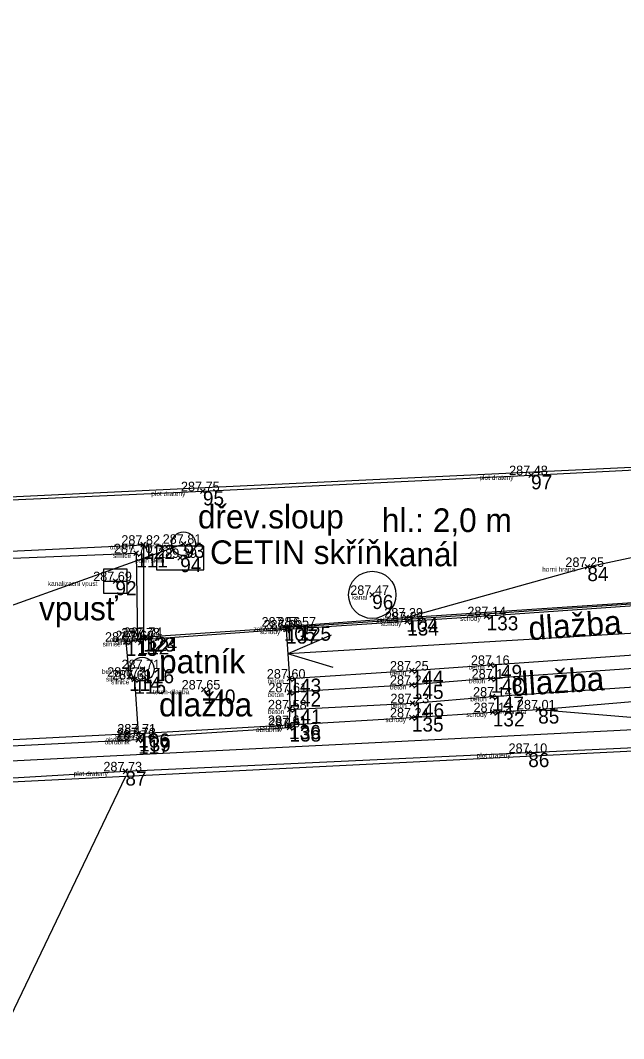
# Model space of a CAD drawing. Extents: x -456675 to -456278, y -1112395 to -1112217.
# Drawn here: x -456580.98 to -456568.22, y -1112310.75 to -1112289.23 of the extents above; entities that cross this region are included whole.
import ezdxf

# ---------------------------------------------------------------- set-up
doc = ezdxf.new("R2010")
doc.units = 0
for name, color, linetype in [('Cislo_bodu', 7, 'Continuous'), ('g_beton', 7, 'Continuous'), ('g_CETIN', 7, 'Continuous'), ('g_chodniky', 7, 'Continuous'), ('g_dalsi_prvky_polohopisu', 7, 'Continuous'), ('g_elektrina', 7, 'Continuous'), ('g_kanalizace', 7, 'Continuous'), ('g_komunikace', 7, 'Continuous'), ('g_obrubnik', 7, 'Continuous'), ('g_ploty', 7, 'Continuous'), ('g_schody', 7, 'Continuous'), ('g_terenni_hrany', 7, 'Continuous'), ('g_zabradli', 7, 'Continuous'), ('Katastralni_mapa', 7, 'Continuous'), ('Kod_bodu', 7, 'Continuous'), ('Vyska_bodu', 7, 'Continuous'), ('Znacka_bodu', 7, 'Continuous')]:
    doc.layers.add(name, color=color, linetype=linetype)

msp = doc.modelspace()

# ---------------------------------------------------------------- linework, layer by layer
at = {"layer": 'g_beton'}
for points in [[(-456575.29, -1112303.14), (-456572.7, -1112302.97), (-456571.04, -1112302.85), (-456563.45, -1112302.32), (-456560.22, -1112302.34)], [(-456560.23, -1112302.68), (-456563.48, -1112302.61), (-456571.03, -1112303.14), (-456572.7, -1112303.27), (-456575.29, -1112303.43)], [(-456575.28, -1112303.79), (-456572.69, -1112303.66), (-456571, -1112303.52), (-456563.54, -1112303.01), (-456560.25, -1112303.02)]]:
    msp.add_lwpolyline(points, dxfattribs=at)
at = {"layer": 'g_CETIN'}
msp.add_line((-456591.85, -1112305.42), (-456577.53, -1112300.29), dxfattribs=at)
msp.add_lwpolyline([(-456578.1, -1112300.84), (-456577.1, -1112300.84), (-456577.1, -1112300.34), (-456578.1, -1112300.34)], close=True, dxfattribs=at)
msp.add_circle((-456577.53, -1112300.29), 0.25, dxfattribs=at)
at = {"layer": 'g_chodniky'}
for p, q in [((-456575.36, -1112302.1), (-456578.5, -1112302.33)), ((-456578.49, -1112304.3), (-456575.3, -1112304.12))]:
    msp.add_line(p, q, dxfattribs=at)
at = {"layer": 'g_dalsi_prvky_polohopisu'}
for radius in [0.25, 0.0005]:
    msp.add_circle((-456578.401, -1112302.94), radius, dxfattribs=at)
at = {"layer": 'g_elektrina'}
msp.add_line((-456591.85, -1112305.42), (-456562.97, -1112303.96), dxfattribs=at)
at = {"layer": 'g_kanalizace'}
msp.add_line((-456579.22, -1112301.08), (-456578.72, -1112301.08), dxfattribs=at)
msp.add_lwpolyline([(-456579.22, -1112301.331), (-456578.72, -1112301.331), (-456578.72, -1112300.829), (-456579.22, -1112300.829)], close=True, dxfattribs=at)
msp.add_circle((-456573.54, -1112301.37), 0.5, dxfattribs=at)
at = {"layer": 'g_komunikace'}
msp.add_lwpolyline([(-456589.51, -1112300.93), (-456583.59, -1112300.69), (-456578.53, -1112300.49), (-456578.5, -1112302.33), (-456578.75, -1112302.36), (-456578.68, -1112303.1), (-456578.57, -1112303.16), (-456578.49, -1112304.3), (-456584.06, -1112304.58), (-456589.75, -1112304.84)], dxfattribs=at)
at = {"layer": 'g_obrubnik'}
msp.add_line((-456578.47, -1112304.38), (-456575.29, -1112304.17), dxfattribs=at)
for points in [[(-456589.47, -1112300.79), (-456583.42, -1112300.55), (-456578.38, -1112300.31), (-456578.38, -1112302.27)], [(-456578.33, -1112302.26), (-456575.08, -1112302.04), (-456563.53, -1112301.25), (-456560.31, -1112301.08)], [(-456589.79, -1112304.97), (-456584.14, -1112304.71), (-456578.49, -1112304.43)]]:
    msp.add_lwpolyline(points, dxfattribs=at)
at = {"layer": 'g_ploty'}
for points in [[(-456588.66, -1112299.7), (-456577.12, -1112299.18), (-456570.18, -1112298.84), (-456563.86, -1112298.52), (-456563.69, -1112291.41), (-456563.68, -1112287.66)], [(-456564.24, -1112317.5), (-456564.14, -1112310.05), (-456564.09, -1112304.42), (-456570.24, -1112304.71), (-456578.76, -1112305.1), (-456590.32, -1112305.79)]]:
    msp.add_lwpolyline(points, dxfattribs=at)
at = {"layer": 'g_schody'}
for p in [(-456560.195, -1112301.72), (-456574.407, -1112302.223), (-456574.367, -1112302.906)]:
    msp.add_line(p, (-456575.325, -1112302.62), dxfattribs=at)
msp.add_lwpolyline([(-456560.17, -1112301.1), (-456563.43, -1112301.31), (-456565.06, -1112301.4), (-456571.12, -1112301.82), (-456572.8, -1112301.93), (-456575.36, -1112302.1), (-456575.29, -1112303.14), (-456575.29, -1112303.43), (-456575.28, -1112303.79), (-456575.3, -1112304.12), (-456572.7, -1112303.96), (-456570.99, -1112303.85), (-456570.03, -1112303.79), (-456564.96, -1112303.36), (-456563.51, -1112303.3), (-456560.26, -1112303.32)], dxfattribs=at)
at = {"layer": 'g_terenni_hrany'}
for points in [[(-456572.82, -1112301.85), (-456568.99, -1112300.78), (-456563.73, -1112299.66), (-456563.86, -1112298.52)], [(-456570.03, -1112303.79), (-456563.38, -1112304.34), (-456564.14, -1112310.05)]]:
    msp.add_lwpolyline(points, dxfattribs=at)
at = {"layer": 'g_zabradli'}
msp.add_lwpolyline([(-456575.41, -1112302.04), (-456572.82, -1112301.85), (-456563.46, -1112301.23), (-456561.81, -1112301.12), (-456560.67, -1112301.04)], dxfattribs=at)
at = {"layer": 'Katastralni_mapa'}
for points in [[(-456563.92, -1112298.48), (-456593.04, -1112299.87)], [(-456578.75, -1112305.2), (-456564.06, -1112304.47)], [(-456600.55, -1112306.28), (-456578.75, -1112305.2)], [(-456590.54, -1112329.78), (-456578.75, -1112305.2)]]:
    msp.add_lwpolyline(points, dxfattribs=at)
at = {"layer": 'Znacka_bodu'}
for p, q in [((-456570.18, -1112298.84), (-456570.23, -1112298.79)), ((-456570.18, -1112298.84), (-456570.23, -1112298.89)), ((-456570.18, -1112298.84), (-456570.13, -1112298.79)), ((-456570.18, -1112298.84), (-456570.13, -1112298.89)), ((-456577.12, -1112299.18), (-456577.17, -1112299.13)), ((-456577.12, -1112299.18), (-456577.07, -1112299.13)), ((-456577.12, -1112299.18), (-456577.17, -1112299.23)), ((-456577.12, -1112299.18), (-456577.07, -1112299.23)), ((-456578.53, -1112300.49), (-456578.58, -1112300.44)), ((-456578.53, -1112300.49), (-456578.48, -1112300.44)), ((-456578.38, -1112300.31), (-456578.43, -1112300.26)), ((-456578.38, -1112300.31), (-456578.43, -1112300.36)), ((-456578.38, -1112300.31), (-456578.33, -1112300.26)), ((-456578.38, -1112300.31), (-456578.33, -1112300.36)), ((-456577.53, -1112300.29), (-456577.58, -1112300.24)), ((-456577.53, -1112300.29), (-456577.58, -1112300.34)), ((-456577.53, -1112300.29), (-456577.48, -1112300.24)), ((-456577.53, -1112300.29), (-456577.48, -1112300.34)), ((-456578.53, -1112300.49), (-456578.58, -1112300.54)), ((-456578.53, -1112300.49), (-456578.48, -1112300.54)), ((-456577.6, -1112300.59), (-456577.65, -1112300.54)), ((-456577.6, -1112300.59), (-456577.65, -1112300.64)), ((-456577.6, -1112300.59), (-456577.55, -1112300.54)), ((-456577.6, -1112300.59), (-456577.55, -1112300.64)), ((-456568.99, -1112300.78), (-456569.04, -1112300.73)), ((-456568.99, -1112300.78), (-456569.04, -1112300.83)), ((-456568.99, -1112300.78), (-456568.94, -1112300.73)), ((-456568.99, -1112300.78), (-456568.94, -1112300.83)), ((-456578.97, -1112301.08), (-456579.02, -1112301.03)), ((-456578.97, -1112301.08), (-456579.02, -1112301.13)), ((-456578.97, -1112301.08), (-456578.92, -1112301.03)), ((-456578.97, -1112301.08), (-456578.92, -1112301.13)), ((-456573.54, -1112301.37), (-456573.59, -1112301.32)), ((-456573.54, -1112301.37), (-456573.59, -1112301.42)), ((-456573.54, -1112301.37), (-456573.49, -1112301.32)), ((-456573.54, -1112301.37), (-456573.49, -1112301.42)), ((-456572.82, -1112301.85), (-456572.87, -1112301.8)), ((-456572.82, -1112301.85), (-456572.87, -1112301.9)), ((-456572.8, -1112301.93), (-456572.85, -1112301.88)), ((-456572.8, -1112301.93), (-456572.85, -1112301.98)), ((-456572.82, -1112301.85), (-456572.77, -1112301.8)), ((-456572.82, -1112301.85), (-456572.77, -1112301.9)), ((-456572.8, -1112301.93), (-456572.75, -1112301.88)), ((-456572.8, -1112301.93), (-456572.75, -1112301.98)), ((-456571.12, -1112301.82), (-456571.17, -1112301.77)), ((-456571.12, -1112301.82), (-456571.17, -1112301.87)), ((-456571.12, -1112301.82), (-456571.07, -1112301.77)), ((-456571.12, -1112301.82), (-456571.07, -1112301.87)), ((-456575.41, -1112302.04), (-456575.46, -1112301.99)), ((-456575.41, -1112302.04), (-456575.46, -1112302.09)), ((-456575.41, -1112302.04), (-456575.36, -1112301.99)), ((-456575.41, -1112302.04), (-456575.36, -1112302.09)), ((-456575.36, -1112302.1), (-456575.41, -1112302.05)), ((-456575.36, -1112302.1), (-456575.41, -1112302.15)), ((-456575.36, -1112302.1), (-456575.31, -1112302.05)), ((-456575.36, -1112302.1), (-456575.31, -1112302.15)), ((-456575.08, -1112302.04), (-456575.13, -1112301.99)), ((-456575.08, -1112302.04), (-456575.13, -1112302.09)), ((-456575.08, -1112302.04), (-456575.03, -1112301.99)), ((-456575.08, -1112302.04), (-456575.03, -1112302.09)), ((-456578.75, -1112302.36), (-456578.8, -1112302.31)), ((-456578.75, -1112302.36), (-456578.8, -1112302.41)), ((-456578.75, -1112302.36), (-456578.7, -1112302.31)), ((-456578.75, -1112302.36), (-456578.7, -1112302.41)), ((-456578.5, -1112302.33), (-456578.55, -1112302.28)), ((-456578.5, -1112302.33), (-456578.55, -1112302.38)), ((-456578.5, -1112302.33), (-456578.45, -1112302.28)), ((-456578.5, -1112302.33), (-456578.45, -1112302.38)), ((-456578.38, -1112302.27), (-456578.43, -1112302.22)), ((-456578.38, -1112302.27), (-456578.43, -1112302.32)), ((-456578.33, -1112302.26), (-456578.38, -1112302.21)), ((-456578.38, -1112302.27), (-456578.33, -1112302.22)), ((-456578.33, -1112302.26), (-456578.38, -1112302.31)), ((-456578.38, -1112302.27), (-456578.33, -1112302.32)), ((-456578.33, -1112302.26), (-456578.28, -1112302.21)), ((-456578.33, -1112302.26), (-456578.28, -1112302.31)), ((-456571.04, -1112302.85), (-456571.09, -1112302.8)), ((-456571.04, -1112302.85), (-456570.99, -1112302.8)), ((-456578.4, -1112302.94), (-456578.45, -1112302.89)), ((-456578.4, -1112302.94), (-456578.45, -1112302.99)), ((-456578.4, -1112302.94), (-456578.35, -1112302.89)), ((-456578.4, -1112302.94), (-456578.35, -1112302.99)), ((-456572.7, -1112302.97), (-456572.75, -1112302.92)), ((-456572.7, -1112302.97), (-456572.75, -1112303.02)), ((-456572.7, -1112302.97), (-456572.65, -1112302.92)), ((-456572.7, -1112302.97), (-456572.65, -1112303.02)), ((-456571.04, -1112302.85), (-456571.09, -1112302.9)), ((-456571.04, -1112302.85), (-456570.99, -1112302.9)), ((-456578.68, -1112303.1), (-456578.73, -1112303.05)), ((-456578.68, -1112303.1), (-456578.73, -1112303.15)), ((-456578.68, -1112303.1), (-456578.63, -1112303.05)), ((-456578.68, -1112303.1), (-456578.63, -1112303.15)), ((-456578.57, -1112303.16), (-456578.62, -1112303.11)), ((-456578.57, -1112303.16), (-456578.62, -1112303.21)), ((-456578.57, -1112303.16), (-456578.52, -1112303.11)), ((-456578.57, -1112303.16), (-456578.52, -1112303.21)), ((-456575.29, -1112303.14), (-456575.34, -1112303.09)), ((-456575.29, -1112303.14), (-456575.34, -1112303.19)), ((-456575.29, -1112303.14), (-456575.24, -1112303.09)), ((-456575.29, -1112303.14), (-456575.24, -1112303.19)), ((-456572.7, -1112303.27), (-456572.75, -1112303.22)), ((-456572.7, -1112303.27), (-456572.65, -1112303.22)), ((-456571.03, -1112303.14), (-456571.08, -1112303.09)), ((-456571.03, -1112303.14), (-456571.08, -1112303.19)), ((-456571.03, -1112303.14), (-456570.98, -1112303.09)), ((-456571.03, -1112303.14), (-456570.98, -1112303.19)), ((-456577.1, -1112303.37), (-456577.15, -1112303.32)), ((-456577.1, -1112303.37), (-456577.15, -1112303.42)), ((-456577.1, -1112303.37), (-456577.05, -1112303.32)), ((-456577.1, -1112303.37), (-456577.05, -1112303.42)), ((-456575.29, -1112303.43), (-456575.34, -1112303.38)), ((-456575.29, -1112303.43), (-456575.34, -1112303.48)), ((-456575.29, -1112303.43), (-456575.24, -1112303.38)), ((-456575.29, -1112303.43), (-456575.24, -1112303.48)), ((-456572.7, -1112303.27), (-456572.75, -1112303.32)), ((-456572.7, -1112303.27), (-456572.65, -1112303.32)), ((-456572.69, -1112303.66), (-456572.74, -1112303.61)), ((-456572.69, -1112303.66), (-456572.74, -1112303.71)), ((-456572.69, -1112303.66), (-456572.64, -1112303.61)), ((-456572.69, -1112303.66), (-456572.64, -1112303.71)), ((-456571, -1112303.52), (-456571.05, -1112303.47)), ((-456571, -1112303.52), (-456571.05, -1112303.57)), ((-456571, -1112303.52), (-456570.95, -1112303.47)), ((-456571, -1112303.52), (-456570.95, -1112303.57)), ((-456575.28, -1112303.79), (-456575.33, -1112303.74)), ((-456575.28, -1112303.79), (-456575.33, -1112303.84)), ((-456575.28, -1112303.79), (-456575.23, -1112303.74)), ((-456575.28, -1112303.79), (-456575.23, -1112303.84)), ((-456570.99, -1112303.85), (-456571.04, -1112303.8)), ((-456570.99, -1112303.85), (-456571.04, -1112303.9)), ((-456570.99, -1112303.85), (-456570.94, -1112303.8)), ((-456570.99, -1112303.85), (-456570.94, -1112303.9)), ((-456570.03, -1112303.79), (-456570.08, -1112303.74)), ((-456570.03, -1112303.79), (-456570.08, -1112303.84)), ((-456570.03, -1112303.79), (-456569.98, -1112303.74)), ((-456570.03, -1112303.79), (-456569.98, -1112303.84)), ((-456575.3, -1112304.12), (-456575.35, -1112304.07)), ((-456575.3, -1112304.12), (-456575.25, -1112304.07)), ((-456572.7, -1112303.96), (-456572.75, -1112303.91)), ((-456572.7, -1112303.96), (-456572.75, -1112304.01)), ((-456572.7, -1112303.96), (-456572.65, -1112303.91)), ((-456572.7, -1112303.96), (-456572.65, -1112304.01)), ((-456578.49, -1112304.3), (-456578.54, -1112304.25)), ((-456578.49, -1112304.3), (-456578.54, -1112304.35)), ((-456578.49, -1112304.3), (-456578.44, -1112304.25)), ((-456578.49, -1112304.3), (-456578.44, -1112304.35)), ((-456575.3, -1112304.12), (-456575.35, -1112304.17)), ((-456575.29, -1112304.17), (-456575.34, -1112304.12)), ((-456575.29, -1112304.17), (-456575.34, -1112304.22)), ((-456575.3, -1112304.12), (-456575.25, -1112304.17)), ((-456575.29, -1112304.17), (-456575.24, -1112304.12)), ((-456575.29, -1112304.17), (-456575.24, -1112304.22)), ((-456578.49, -1112304.43), (-456578.54, -1112304.38)), ((-456578.49, -1112304.43), (-456578.54, -1112304.48)), ((-456578.47, -1112304.38), (-456578.52, -1112304.33)), ((-456578.47, -1112304.38), (-456578.52, -1112304.43)), ((-456578.49, -1112304.43), (-456578.44, -1112304.38)), ((-456578.49, -1112304.43), (-456578.44, -1112304.48)), ((-456578.47, -1112304.38), (-456578.42, -1112304.33)), ((-456578.47, -1112304.38), (-456578.42, -1112304.43)), ((-456570.24, -1112304.71), (-456570.29, -1112304.66)), ((-456570.24, -1112304.71), (-456570.29, -1112304.76)), ((-456570.24, -1112304.71), (-456570.19, -1112304.66)), ((-456570.24, -1112304.71), (-456570.19, -1112304.76)), ((-456578.76, -1112305.1), (-456578.81, -1112305.05)), ((-456578.76, -1112305.1), (-456578.81, -1112305.15)), ((-456578.76, -1112305.1), (-456578.71, -1112305.05)), ((-456578.76, -1112305.1), (-456578.71, -1112305.15))]:
    msp.add_line(p, q, dxfattribs=at)

# ---------------------------------------------------------------- texts
at = {"layer": 'Cislo_bodu'}
for s, p in [('97', (-456570.18, -1112299.14)), ('95', (-456577.12, -1112299.48)), ('122', (-456578.38, -1112300.61)), ('93', (-456577.53, -1112300.59)), ('111', (-456578.53, -1112300.79)), ('94', (-456577.6, -1112300.89)), ('84', (-456568.99, -1112301.08)), ('92', (-456578.97, -1112301.38)), ('96', (-456573.54, -1112301.67)), ('104', (-456572.82, -1112302.15)), ('134', (-456572.8, -1112302.23)), ('133', (-456571.12, -1112302.12)), ('105', (-456575.41, -1112302.34)), ('137', (-456575.36, -1112302.4)), ('125', (-456575.08, -1112302.34)), ('113', (-456578.75, -1112302.66)), ('112', (-456578.5, -1112302.63)), ('123', (-456578.38, -1112302.57)), ('124', (-456578.33, -1112302.56)), ('116', (-456578.4, -1112303.24)), ('144', (-456572.7, -1112303.27)), ('149', (-456571.04, -1112303.15)), ('114', (-456578.68, -1112303.4)), ('115', (-456578.57, -1112303.46)), ('143', (-456575.29, -1112303.44)), ('148', (-456571.03, -1112303.44)), ('140', (-456577.1, -1112303.67)), ('142', (-456575.29, -1112303.73)), ('145', (-456572.7, -1112303.57)), ('146', (-456572.69, -1112303.96)), ('147', (-456571, -1112303.82)), ('141', (-456575.28, -1112304.09)), ('132', (-456570.99, -1112304.15)), ('85', (-456570.03, -1112304.09)), ('135', (-456572.7, -1112304.26)), ('106', (-456578.49, -1112304.6)), ('136', (-456575.3, -1112304.42)), ('138', (-456575.29, -1112304.47)), ('117', (-456578.49, -1112304.73)), ('139', (-456578.47, -1112304.68)), ('86', (-456570.24, -1112305.01)), ('87', (-456578.76, -1112305.4))]:
    msp.add_text(s, height=0.3, dxfattribs=at).set_placement(p)
at = {"layer": 'g_CETIN'}
for s, p in [('dřev.sloup', (-456577.226, -1112299.967)), ('CETIN skříň', (-456576.969, -1112300.719))]:
    msp.add_text(s, height=0.5, dxfattribs=at).set_placement(p)
at = {"layer": 'g_chodniky'}
msp.add_text('dlažba', height=0.5, dxfattribs=at).set_placement((-456578.048, -1112303.94))
at = {"layer": 'g_dalsi_prvky_polohopisu'}
msp.add_text('patník', height=0.5, dxfattribs=at).set_placement((-456578.048, -1112303.028))
at = {"layer": 'g_kanalizace'}
for s, p in [('hl.: 2,0 m', (-456573.337, -1112300.043)), ('kanál', (-456573.312, -1112300.765)), ('vpusť', (-456580.585, -1112301.908))]:
    msp.add_text(s, height=0.5, dxfattribs=at).set_placement(p)
at = {"layer": 'g_schody'}
for rotation, p in [(4.1708, (-456570.218, -1112302.332)), (3.7062, (-456570.587, -1112303.513))]:
    msp.add_text('dlažba', height=0.5, rotation=rotation, dxfattribs=at).set_placement(p)
at = {"layer": 'Kod_bodu'}
for s, p in [('plot drateny', (-456571.273, -1112298.94)), ('plot drateny', (-456578.213, -1112299.28)), ('obrubnik', (-456579.09, -1112300.41)), ('drev.sloup', (-456578.37, -1112300.39)), ('silnice', (-456579.021, -1112300.59)), ('cetin skrin', (-456578.555, -1112300.69)), ('horni hrana', (-456569.946, -1112300.88)), ('kanalizacni vpust', (-456580.401, -1112301.18)), ('kanal', (-456573.972, -1112301.47)), ('zabradli', (-456573.462, -1112301.95)), ('schody', (-456573.362, -1112302.03)), ('schody', (-456571.682, -1112301.92)), ('zabradli', (-456576.052, -1112302.14)), ('schody', (-456575.922, -1112302.2)), ('obrubnik', (-456575.79, -1112302.14)), ('silnice', (-456579.241, -1112302.46)), ('obrubnik', (-456579.09, -1112302.37)), ('obrubnik', (-456579.04, -1112302.36)), ('silnice', (-456578.991, -1112302.43)), ('bet.patnik', (-456579.257, -1112303.04)), ('beton', (-456573.165, -1112303.07)), ('beton', (-456571.505, -1112302.95)), ('silnice', (-456579.171, -1112303.2)), ('silnice', (-456579.061, -1112303.26)), ('beton', (-456575.755, -1112303.24)), ('beton', (-456571.495, -1112303.24)), ('teren-dlazba', (-456578.177, -1112303.47)), ('beton', (-456575.755, -1112303.53)), ('beton', (-456573.165, -1112303.37)), ('beton', (-456573.155, -1112303.76)), ('beton', (-456571.465, -1112303.62)), ('beton', (-456575.745, -1112303.89)), ('schody', (-456571.552, -1112303.95)), ('horni hrana', (-456570.986, -1112303.89)), ('schody', (-456573.262, -1112304.06)), ('silnice', (-456578.981, -1112304.4)), ('obrubnik', (-456576, -1112304.27)), ('schody', (-456575.862, -1112304.22)), ('obrubnik', (-456579.2, -1112304.53)), ('obrubnik', (-456579.18, -1112304.48)), ('plot drateny', (-456571.333, -1112304.81)), ('plot drateny', (-456579.853, -1112305.2))]:
    msp.add_text(s, height=0.1, dxfattribs=at).set_placement(p)
at = {"layer": 'Vyska_bodu'}
for s, p in [('287.48', (-456570.645, -1112298.84)), ('287.75', (-456577.585, -1112299.18)), ('287.82', (-456578.845, -1112300.31)), ('287.81', (-456577.971, -1112300.29)), ('287.70', (-456579.003, -1112300.49)), ('289.39', (-456578.066, -1112300.59)), ('287.25', (-456569.455, -1112300.78)), ('287.69', (-456579.441, -1112301.08)), ('287.47', (-456574.005, -1112301.37)), ('287.29', (-456573.285, -1112301.85)), ('287.26', (-456573.27, -1112301.93)), ('287.14', (-456571.528, -1112301.82)), ('287.56', (-456575.88, -1112302.04)), ('287.60', (-456575.839, -1112302.1)), ('287.57', (-456575.545, -1112302.04)), ('287.71', (-456579.191, -1112302.36)), ('287.69', (-456578.971, -1112302.33)), ('287.78', (-456578.845, -1112302.27)), ('287.74', (-456578.795, -1112302.26)), ('287.71', (-456578.841, -1112302.94)), ('287.25', (-456573.165, -1112302.97)), ('287.16', (-456571.453, -1112302.85)), ('287.72', (-456579.145, -1112303.1)), ('287.69', (-456579.041, -1112303.16)), ('287.60', (-456575.769, -1112303.14)), ('287.14', (-456571.438, -1112303.14)), ('287.65', (-456577.57, -1112303.37)), ('287.61', (-456575.736, -1112303.43)), ('287.24', (-456573.165, -1112303.27)), ('287.23', (-456573.155, -1112303.66)), ('287.14', (-456571.408, -1112303.52)), ('287.58', (-456575.745, -1112303.79)), ('287.12', (-456571.398, -1112303.85)), ('287.01', (-456570.48, -1112303.79)), ('287.24', (-456573.165, -1112303.96)), ('287.71', (-456578.931, -1112304.3)), ('287.61', (-456575.746, -1112304.12)), ('287.61', (-456575.736, -1112304.17)), ('287.78', (-456578.955, -1112304.43)), ('287.72', (-456578.935, -1112304.38)), ('287.10', (-456570.657, -1112304.71)), ('287.73', (-456579.225, -1112305.1))]:
    msp.add_text(s, height=0.2, dxfattribs=at).set_placement(p)

doc.saveas('drawing.dxf')
